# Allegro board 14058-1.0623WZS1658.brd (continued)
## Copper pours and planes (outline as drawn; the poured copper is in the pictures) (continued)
SB3V on L4: 140.15,234.43 140.4,234.68 144.09,234.68 144.21,234.56 144.21,231.25 142.69,229.73 108.78,229.73 107.89,230.62 107.89,231.63 110.69,234.43
SB5V on BOTTOM: 107.89,55.61 107.51,55.99 107.51,56.12 108.15,56.76 108.15,59.68 109.16,59.68 109.42,59.42 109.42,56.88 108.15,55.61
SB5V on BOTTOM: 63.19,51.68 62.93,51.93 62.93,55.28 62.97,55.32 62.97,55.9 63.32,56.25 69.28,56.25 71.06,54.47 72.46,54.47 72.84,54.09 72.84,51.93 71.19,51.93 70.88,52.23 69.74,52.23 69.28,52.69 68.52,52.69 68.14,52.31 65.22,52.31 64.59,51.68 ; 4 cut-outs
SB5V on BOTTOM: 93.16,63.11 92.91,63.36 92.91,65.65 91.76,66.79 91.76,70.6 94.81,73.65 96.97,73.65 97.22,73.39 97.22,72.5 96.97,72.25 95.45,72.25 93.03,69.84 93.03,67.68 94.05,66.66 94.05,63.36 93.8,63.11
SB5V on BOTTOM: 45.92,254.49 45.66,254.75 45.66,256.91 46.81,258.05 54.43,258.05 54.68,257.8 54.68,257.03 54.3,256.65 48.58,256.65 47.31,255.38 47.31,254.88 46.93,254.49
SB5V on L3: 62.81,52.69 62.81,51.8 63.06,51.55 79.57,51.55 85.67,57.64 89.99,57.64 91.13,58.79 91.13,60.06 93.03,61.96 93.03,62.72 93.54,63.23 93.8,63.23 94.05,63.49 94.05,63.99 93.8,64.25 92.78,64.25 91.38,62.85 90.37,62.85 87.45,59.93 86.05,59.93 79.06,52.95 63.06,52.95
SD_VDD2 on BOTTOM: 197.68,151.75 197.55,151.88 197.55,152.77 198.19,153.4 199.21,153.4 199.59,153.78 199.59,154.55 199.84,154.8 199.84,155.31 200.22,155.69 201.11,155.69 201.75,156.32 202.13,156.32 202.38,156.07 202.38,155.69 200.98,154.29 200.98,152.89 199.84,151.75 ; 3 cut-outs
SLEEVE_CON on TOP: 187.9,74.28 187.65,74.54 187.65,75.17 187.78,75.3 194.51,75.3 194.63,75.17 194.63,74.54 194.38,74.28 ; 4 cut-outs
SPKR_OUT_L+ on TOP: 162.38,28.56 161.99,28.94 161.99,30.47 162.88,31.36 166.57,31.36 166.69,31.23 166.69,30.21 166.19,29.7 164.79,29.7 163.65,28.56 ; 5 cut-outs
USBVCC01 on TOP: 186.25,117.21 185.74,117.72 184.98,117.72 184.73,117.97 184.73,119.24 185.11,119.62 188.79,119.62 188.92,119.75 189.81,119.75 190.32,120.26 193.11,120.26 193.36,120 193.36,119.37 192.73,118.73 191.46,118.73 189.93,117.21 ; 2 cut-outs
USBVCC01 on TOP: 176.85,90.16 176.47,90.54 176.47,99.3 177.62,100.44 182.57,100.44 184.09,101.97 191.2,101.97 193.74,99.43 193.74,97.78 192.98,97.01 184.47,97.01 182.06,94.6 182.06,94.22 180.28,92.44 179.27,92.44 178.76,91.93 178.76,90.54 178.38,90.16 ; 2 cut-outs
USBVCC01 on BOTTOM: 179.14,95.36 178.63,95.87 178.63,99.43 179.01,99.81 180.79,99.81 182.31,101.33 187.14,101.33 187.52,101.71 187.52,105.14 186.76,105.9 185.87,105.9 185.49,106.29 185.49,120.26 186.76,121.53 191.97,121.53 193.24,120.26 193.24,118.35 192.98,118.1 191.97,118.1 191.59,117.72 191.59,112.25 192.35,111.49 193.24,111.49 193.74,110.98 193.74,97.78 193.24,97.27 182.95,97.27 181.04,95.36
USBVCC89 on TOP: 116.02,15.35 115.96,15.42 115.39,15.42 113.99,16.81 113.99,23.35 112.21,25.13 112.21,26.15 112.85,26.78 116.02,26.78 116.15,26.91 116.27,26.91 116.78,27.42 121.61,27.42 122.12,26.91 122.12,23.61 121.99,23.48 121.99,19.04 123.51,17.51 123.51,15.61 123.26,15.35 ; 8 cut-outs
USBVCC89 on BOTTOM: 115.51,14.46 115.13,14.85 115.13,17.51 115.39,17.77 116.53,17.77 117.04,17.26 118.94,17.26 119.96,18.27 135.2,18.27 135.96,17.51 135.96,16.12 135.32,15.48 120.85,15.48 119.83,14.46
USBVCC1011 on TOP: 109.54,27.04 108.27,28.31 108.27,34.66 109.16,35.55 109.8,35.55 110.43,36.18 110.43,38.85 110.56,38.98 111.7,38.98 111.96,38.72 111.96,38.21 112.08,38.09 116.27,38.09 123.51,45.33 134.94,45.33 136.34,43.93 136.34,42.66 136.98,42.02 136.98,38.59 136.85,38.47 133.29,38.47 133.04,38.72 131.39,38.72 128.47,41.64 125.04,41.64 124.4,41.01 124.4,40.63 121.74,37.96 120.47,37.96 116.78,34.28 116.78,27.93 115.89,27.04 ; 8 cut-outs
USBVCCTP on TOP: 14.29,130.8 14.17,130.92 14.17,132.32 14.29,132.45 15.94,132.45 16.07,132.32 16.07,131.94 14.93,130.8
USBVCCTP on BOTTOM: 14.17,130.8 13.79,131.18 13.79,137.02 14.04,137.27 14.8,137.27 15.06,137.02 15.06,131.05 14.8,130.8
V_1P5_HDMI on TOP: 163.06,47.38 163.06,48.2 163.31,48.45 164,48.45 164.2,48.25 164.2,47.64 163.95,47.38
V_1P5_HDMI on TOP: 157.3,42.79 157.17,42.91 157.17,43.67 157.55,44.06 157.68,44.06 157.8,43.93 158.69,43.93 158.69,43.29 158.18,42.79
V_1P5_HDMI on TOP: 163.62,42.81 163.01,43.42 163.01,43.93 163.77,43.93 164.2,43.5 165.09,43.5 165.17,43.42 165.17,42.96 165.02,42.81
V_1P5_HDMI on TOP: 147.77,45.83 146.12,47.48 144.72,47.48 144.34,47.87 142.94,47.87 142.18,47.1 141.29,47.1 141.17,47.23 141.17,47.99 142.18,49.01 144.21,49.01 144.72,49.52 149.42,49.52 149.68,49.26 149.68,46.34 149.17,45.83 ; 3 cut-outs
V_1P5_HDMI on BOTTOM: 164.03,41.52 162.25,43.29 158.82,43.29 158.18,42.66 155.64,42.66 153.23,45.07 147.52,45.07 147.14,45.45 147.14,47.23 147.52,47.61 155.77,47.61 155.9,47.48 155.9,46.85 155.77,46.72 155.14,46.72 154.88,46.47 154.88,45.07 156.41,43.55 157.68,43.55 158.31,44.18 162.88,44.18 164.66,42.4 165.8,42.4 165.93,42.28 165.93,41.64 165.8,41.52 ; 1 cut-out
V_1P05_LAN on TOP: 63.57,24.09 63.47,24.19 63.47,24.52 62.98,25.01 62.98,25.89 63.16,25.89 64.18,24.88 64.18,24.17 64.1,24.09
V_1P05_LAN on BOTTOM: 60.01,23.86 59.51,24.37 57.73,24.37 56.71,25.39 56.71,31.61 56.97,31.86 61.16,31.86 61.79,31.23 61.79,30.47 61.54,30.21 60.01,30.21 59.76,29.96 59.12,29.96 58.74,30.34 58.11,30.34 57.98,30.21 57.98,28.05 58.36,27.67 59.12,27.67 59.25,27.55 59.25,26.15 59.63,25.77 64.59,25.77 64.71,25.64 64.71,24.24 64.33,23.86 ; 8 cut-outs
V_3_CARD on BOTTOM: 179.27,140.24 178.76,140.75 178.76,141.13 179.01,141.39 180.54,141.39 180.74,141.59 181.63,141.59 181.91,141.87 181.91,142.2 182.06,142.35 182.36,142.35 182.7,142.02 182.82,142.02 183.2,141.64 183.2,140.5 182.95,140.24 ; 4 cut-outs
V_3P3_A on TOP: 75.51,68.06 75.25,68.31 73.09,68.31 68.78,72.63 65.09,72.63 63.06,74.66 61.28,74.66 61.16,74.79 61.16,79.62 61.66,80.12 63.82,80.12 64.78,79.17 64.78,77.9 67,75.68 71.82,75.68 72.84,74.66 74.24,74.66 78.43,70.47 79.19,70.47 80.08,69.58 80.08,68.57 79.57,68.06 ; 2 cut-outs
V_3P3_A on BOTTOM: 102.58,63.59 102.48,63.69 102.48,64.27 102.56,64.35 103.14,64.35 103.4,64.6 103.4,64.91 104.01,65.52 105.99,65.52 106.5,65.01 106.5,64.25 106.24,63.99 105.86,63.99 105.61,64.25 105.61,64.63 105.48,64.76 104.84,64.76 104.54,64.45 104.54,64.2 103.93,63.59
V_3P3_A on BOTTOM: 79.11,67.12 78.3,67.93 77.79,67.93 77.41,68.31 77.41,69.33 77.79,69.71 79.7,69.71 80.08,69.33 80.08,68.13 79.95,68.01 79.95,67.12
V_3P3_A on BOTTOM: 75.38,44.69 74.36,45.71 74.36,50.43 75.35,50.43 75.53,50.25 75.53,49.29 76.4,48.42 76.4,46.09 76.65,45.83 78.3,45.83 78.56,45.58 78.56,44.94 78.3,44.69 ; 4 cut-outs
V_3P3_PCIVAUX on TOP: 135.07,226.55 134.94,226.68 134.94,226.69 134.69,226.95 131.79,226.95 131.66,227.07 131.66,229.61 131.79,229.74 135.85,229.74 136.23,229.36 136.23,228.33 139.9,228.33 140.79,227.44 140.79,227.06 140.28,226.55 ; 8 cut-outs
V_3P3_PCIVAUX on BOTTOM: 135.07,226.05 134.56,226.55 134.56,228.84 135.83,230.11 138.12,230.11 138.25,229.98 138.25,229.7 138.37,229.7 139.99,228.08 145.74,228.08 146.25,228.59 146.25,229.98 146.37,230.11 149.17,230.11 149.42,229.86 149.42,226.55 148.91,226.05
V_5_LCD1 on BOTTOM: 17.6,52.82 17.34,53.07 17.34,53.58 16.96,53.96 16.45,53.96 16.33,54.09 16.33,55.23 16.45,55.36 18.1,55.36 18.36,55.1 19.37,55.1 19.63,54.85 19.63,53.96 19.37,53.71 18.48,53.71 18.23,53.45 18.23,53.07 17.98,52.82 ; 1 cut-out
V_5_LCD2 on BOTTOM: 18.48,55.49 18.1,55.87 16.45,55.87 16.33,55.99 16.33,57.26 17.09,58.03 17.09,58.91 17.47,59.3 18.36,59.3 20.01,57.64 20.01,55.74 19.75,55.49 ; 3 cut-outs
V_5HDD on TOP: 23.82,113.78 22.17,115.43 20.9,115.43 20.39,115.94 20.39,126.22 20.9,126.73 22.68,126.73 23.95,125.46 28.39,125.46 28.77,125.08 28.77,114.16 28.39,113.78 ; 4 cut-outs
V_5P0_A on TOP: 75.13,54.47 74.87,54.72 74.87,60.18 75,60.31 78.94,60.31 79.19,60.06 79.19,55.1 78.56,54.47
V_5P0_A on BOTTOM: 77.59,50.91 77.46,51.04 77.46,51.47 78.05,52.06 78.05,52.82 77.92,52.95 77.03,52.95 76.02,51.93 74.36,51.93 74.36,53.83 75.13,54.6 75.13,62.98 75.99,63.84 75.99,64.73 76.52,65.26 78.05,65.26 78.43,65.65 79.95,65.65 79.95,64.76 80.33,64.38 80.33,51.93 79.95,51.55 78.81,51.55 78.76,51.6 78.63,51.6 77.95,50.91 ; 3 cut-outs
V_19_INV on TOP: 7.69,5.45 7.56,5.57 7.56,11.92 8.57,12.93 12.87,12.93 13.15,12.65 13.15,5.57 13.02,5.45
V_CPU_CORE on TOP: outline of 111 points within 34.99,179.24 83.51,229.09 ; 6 cut-outs
V_CPU_CORE on BOTTOM: 70.17,180.58 69.16,181.6 69.16,182.23 69.41,182.49 79.83,182.49 80.84,183.5 80.91,183.5 80.91,185.69 80.53,186.08 77.03,186.08 76.56,186.55 69.79,186.55 68.56,185.31 63.51,185.31 62.12,183.92 58.14,183.92 57.85,183.63 46.68,183.63 45.79,184.52 40.33,184.52 34.99,189.85 34.99,228.71 35.38,229.09 42.61,229.09 48.58,223.13 48.58,220.71 51.76,217.54 51.76,210.68 58.87,203.57 60.9,203.57 61.28,203.19 61.28,201.15 61.65,200.79 62.57,200.79 62.68,200.68 62.71,200.68 62.88,200.51 62.88,197.51 67.17,193.21 69.1,193.21 69.1,193.19 69.48,192.81 69.48,191.38 69.86,190.99 76.27,190.99 76.78,190.49 76.78,189.22 77.16,188.84 81.35,188.84 81.54,189.03 83.25,187.31 83.25,180.83 83,180.58 ; 8 cut-outs
V_CPU_CORE on L3: 68.15,196.26 64.97,199.43 63.95,199.43 61.34,202.05 61.34,203.19 61.01,203.52 58.91,203.52 51.76,210.68 51.76,220.2 50.62,221.35 50.62,223.76 46.3,228.08 39.95,228.08 38.93,229.09 35.38,229.09 34.99,228.71 34.99,189.85 40.33,184.52 49.09,184.52 51.11,182.5 52.41,182.5 55.7,179.22 81.42,179.22 83.2,181 83.2,189.32 82.49,190.04 73.48,190.04 68.15,195.37
V_CPU_CORE on L4: 38.3,186.04 44.52,186.04 45.92,187.44 48.58,187.44 50.92,189.77 54.88,189.77 55.31,189.34 57.02,189.34 57.3,189.62 62.05,189.62 63.34,188.33 63.34,188.05 64.33,187.06 64.33,181.34 64.2,181.22 64.2,180.33 64.97,179.56 68.78,179.56 69.54,180.33 73.73,180.33 77.67,184.26 77.67,189.85 77.41,190.11 73.86,190.11 68.78,195.19 68.78,197.85 60.01,206.62 60.01,214.74 44.27,230.49 36.01,230.49 34.87,229.35 34.87,189.47
V_CPU_GT on TOP: 69.99,195.09 69.1,195.98 69.1,198.27 64.77,202.61 63.19,202.61 62.94,202.86 62.94,207.66 62.5,208.1 62.5,208.17 62.24,208.43 61.61,208.43 60.38,209.65 60.38,214.75 53.79,221.35 53.79,233.03 60.9,240.14 76.14,240.14 77.16,241.16 77.16,243.32 80.84,247 80.84,250.3 81.48,250.94 90.24,250.94 90.87,250.3 90.87,246.24 91.38,245.73 100.91,245.73 102.43,244.21 106.75,244.21 107.26,243.7 107.26,238.87 103.96,235.57 99.51,235.57 96.84,232.9 96.84,222.49 84.91,210.55 77.03,210.55 76.14,209.66 76.14,204.71 76.55,204.3 76.55,201.57 77.67,200.45 77.67,199.28 78.05,198.9 79.9,198.9 80.28,198.52 80.28,195.22 80.15,195.09 ; 2 cut-outs
V_CPU_GT on BOTTOM: 69.23,195.22 69.1,195.35 69.1,196.87 69.11,196.88 69.03,196.96 69.03,198.27 63.95,203.35 63.9,203.35 62.5,204.74 62.5,205.63 60.38,207.75 60.39,207.76 60.39,214.74 53.79,221.35 53.79,233.03 61.16,240.4 82.62,240.4 87.57,245.35 96.34,245.35 96.72,245.73 100.91,245.73 102.43,244.21 106.75,244.21 107.26,243.7 107.26,238.87 103.96,235.57 99.51,235.57 96.84,232.9 96.84,229.73 88.97,221.86 82.28,221.86 74.94,214.52 74.94,204.11 76.52,202.53 76.52,200.47 78.05,198.94 79.88,198.94 80.28,198.54 80.28,195.24 80.27,195.22
V_CPU_GT on L3: 74.87,213.98 74.87,203.06 75,202.93 75.14,202.93 77.72,200.35 78.76,200.35 80.21,198.9 80.21,197.22 77.42,194.43 77.42,190.8 77.04,190.42 75.89,190.42 75.89,190.52 75.56,190.85 73.43,190.85 69.16,195.12 69.16,198.42 64.21,203.37 63.36,203.37 62.43,204.31 62.43,206.62 60.39,208.65 60.39,214.74 53.79,221.35 53.79,233.03 61.16,240.4 76.4,240.4 77.16,241.16 77.16,243.32 80.84,247 80.84,250.3 81.48,250.94 90.24,250.94 90.87,250.3 90.87,246.24 91.38,245.73 100.91,245.73 102.43,244.21 106.75,244.21 107.26,243.7 107.26,238.87 103.96,235.57 99.51,235.57 96.84,232.9 96.84,230.91 91.09,225.16 86.05,225.16
V_CPU_GT on L4: 76.27,215.89 76.27,213 76.22,212.95 76.27,212.9 76.27,201.26 77.51,200.02 80.17,200.02 80.53,199.66 80.53,194.97 77.42,191.85 77.42,190.8 77.04,190.42 73.86,190.42 69.16,195.12 69.16,198.42 63.26,204.32 63.26,204.36 60.39,207.23 60.39,214.74 53.79,221.35 53.79,233.03 61.16,240.4 76.4,240.4 77.16,241.16 77.16,243.32 80.84,247 80.84,250.3 81.48,250.94 90.24,250.94 90.87,250.3 90.87,246.24 91.38,245.73 100.91,245.73 102.43,244.21 106.75,244.21 107.26,243.7 107.26,238.87 103.96,235.57 99.51,235.57 96.84,232.9 96.84,230.91 92.11,226.17 86.56,226.17
V_CPU_GTX on BOTTOM: 66.11,198.11 65.86,198.36 65.86,198.74 65.47,199.12 64.97,199.12 64.08,200.01 63.32,200.01 63.06,200.27 63.06,200.77 62.81,201.03 62.3,201.03 62.17,201.15 62.17,201.66 61.92,201.92 61.54,201.92 61.41,202.04 61.41,202.42 61.66,202.68 64.33,202.68 66.24,200.77 67.25,200.77 67.76,200.27 67.76,198.49 67.38,198.11
V_CPU_IO on TOP: 66.75,174.67 66.62,174.8 66.62,175.3 66.75,175.43 67,175.43 68.02,176.45 69.85,176.45 71.7,178.29 71.7,179.82 71.82,179.95 71.82,179.98 73.8,179.98 73.93,179.85 73.93,178.83 73.86,178.76 73.86,175.25 73.3,174.69 71.29,174.69 71.09,174.89 70.76,174.89 70.56,174.69 70.38,174.69 69.8,175.27 69.3,175.27 68.73,174.69 68.48,174.69 68.01,175.16 67.37,175.16 66.88,174.67 ; 3 cut-outs
V_CPU_IO on TOP: 82.29,178.73 80.28,180.74 79.64,180.74 79.52,180.87 79.52,182.77 79.64,182.9 80.91,182.9 81.29,182.52 81.29,181.97 81.61,181.65 81.61,180.76 83,179.37 83.39,179.37 84.15,180.13 84.27,180.13 84.53,179.88 84.53,178.99 84.27,178.73
V_CPU_IO on TOP: 79.26,189.25 79.01,189.5 79.01,192.17 79.26,192.43 80.91,192.43 81.29,192.04 81.29,189.63 80.91,189.25
V_CPU_IO on TOP, BOTTOM: 45.79,175.25 45.41,175.63 45.41,180.96 45.66,181.22 48.58,181.22 48.96,180.83 48.96,175.63 48.58,175.25
V_CPU_IO on BOTTOM: 79.57,189.22 79.19,189.6 79.19,192.39 79.44,192.65 80.97,192.65 81.35,192.26 81.35,189.47 81.1,189.22
V_CPU_IO on L3: 55.7,178.8 72.71,178.8 73.73,177.79 73.73,175.75 73.48,175.5 64.46,175.5 61.03,172.07 56.46,172.07 53.79,174.74 47.06,174.74 46.81,174.99 46.81,180.96 47.31,181.47 53.03,181.47
V_CPU_IO on L4: 83.45,189.72 84.09,190.36 84.09,192.38 83,193.46 79.79,193.46 77.99,191.66 77.99,184.04 73.42,179.47 72.15,179.47 71.52,178.84 71.52,175.03 72.4,174.14 76.47,174.14 76.72,174.39 76.72,176.04 77.48,176.8 77.48,177.57 77.87,177.95 82.69,177.95 83.96,179.22 83.96,183.28 83.45,183.79
V_CPU_OPC on TOP: 82.75,194.3 82.37,194.68 82.37,197.22 82.49,197.34 83.25,197.34 83.38,197.22 83.38,196.96 83.25,196.84 83.25,196.71 83.51,196.46 83.51,196.2 83.38,196.07 83.38,195.69 84.02,195.06 84.4,195.06 84.52,195.19 84.78,195.19 84.91,195.06 84.91,194.8 84.4,194.3
V_CPU_OPC on BOTTOM: 80.84,196.07 80.71,196.2 80.71,196.96 81.1,197.34 82.75,197.34 83.13,196.96 83.13,196.33 82.87,196.07
V_CPU_SA on TOP: 37.41,160.51 35.5,162.42 35.5,173.21 35.76,173.47 43.5,173.47 44.01,172.96 44.01,162.17 43.63,161.78 40.71,161.78 39.44,160.51
V_CPU_SA on TOP: 73.73,172.89 73.48,173.14 73.48,173.22 73.45,173.22 72.9,173.78 72.59,173.78 72.39,173.58 71.37,173.58 71.09,173.86 70.69,173.86 70.56,173.73 70.33,173.73 70.2,173.86 69.8,173.86 69.7,173.75 69.39,173.75 69.29,173.86 68.93,173.86 68.83,173.75 68.5,173.75 68.43,173.83 68.04,173.83 67.94,173.73 67.64,173.73 67.51,173.86 67.51,174.24 67.99,174.72 68.3,174.72 68.45,174.57 68.88,174.57 69.01,174.69 69.26,174.69 69.37,174.59 69.72,174.59 69.74,174.57 73.35,174.57 73.48,174.69 73.48,174.7 74.11,175.34 74.11,177.79 75.76,177.79 76.4,178.42 76.4,179.22 76.78,179.6 77.1,179.6 77.27,179.44 78.43,179.44 78.68,179.18 78.68,176.26 77.54,175.12 77.54,173.27 77.16,172.89 ; 4 cut-outs
V_CPU_SA on BOTTOM: 76.02,174.23 75.51,174.74 74.49,174.74 74.24,174.99 74.24,178.42 74.75,178.93 78.68,178.93 79.19,178.42 79.19,176.26 77.16,174.23
V_CPU_SA on L3: 75.25,166.22 67.16,158.14 52.74,158.14 49.73,161.15 37.15,161.15 35.5,162.8 35.5,173.21 35.76,173.47 54.3,173.47 56.42,171.34 61.01,171.34 61.9,172.23 61.9,172.36 64.81,175.27 64.84,175.25 73.98,175.25 74.11,175.37 74.11,177.91 74.29,178.1 78.88,178.1 79.32,177.66 79.32,176.36 76.81,173.85 76.81,172.96 75.25,171.4
V_CPU_SA on L4: 72.28,172.23 72.28,173.63 72.53,173.88 76.47,173.88 76.85,174.26 76.85,175.92 77.61,176.68 77.61,177.44 77.87,177.69 78.63,177.69 78.88,177.44 78.88,176.55 77.87,175.53 77.87,174.39 77.48,174.01 77.48,174 77.01,173.52 77.01,172.26 75.71,170.96 74.06,170.96 72.91,172.11 72.4,172.11
V_SM on TOP: 108.27,124.45 108.02,124.7 108.02,125.59 107,126.61 105.73,126.61 104.34,128 104.34,131.3 104.59,131.56 107.13,131.56 107.26,131.43 107.26,128.64 107.51,128.38 111.96,128.38 114.24,130.67 114.24,136.38 114.88,137.02 121.63,137.02 125.04,133.62 125.04,130.42 121.23,126.61 114.24,126.61 112.08,124.45
V_SM on BOTTOM: 121.61,131.81 116.78,136.64 116.78,153.28 115,155.05 96.34,155.05 88.59,162.8 88.59,180.45 89.48,181.34 89.48,183.2 89.3,183.37 89.1,183.37 88.59,183.88 88.59,191.76 101.42,204.58 125.16,204.58 125.29,204.46 165.3,204.46 166.82,202.93 170.76,202.93 173.42,200.27 173.42,157.47 171.01,155.05 129.23,155.05 125.1,150.93 125.1,133.53 123.39,131.81 ; 59 cut-outs
V_SM_VTT on TOP: 157.8,130.42 155.14,133.08 151.71,133.08 151.07,133.72 151.07,134.86 151.83,135.62 156.28,135.62 158.69,133.21 162.12,133.21 164.53,135.62 169.87,135.62 170,135.5 170,134.23 166.19,130.42
V_SM_VTT on BOTTOM: 145.1,129.53 142.06,132.57 142.06,137.02 142.31,137.27 143.71,137.27 143.96,137.53 144.85,137.53 145.1,137.27 145.1,133.72 145.99,132.83 149.8,132.83 151.83,134.86 165.04,134.86 165.42,135.24 165.42,135.75 165.55,135.88 166.31,135.88 166.44,135.75 168.85,135.75 169.36,135.24 169.36,132.45 168.09,131.18 153.36,131.18 151.71,129.53 ; 7 cut-outs
VOUT_INV on TOP: 25.47,2.91 25.22,3.16 25.22,6.21 25.34,6.34 26.87,6.34 26.99,6.21 26.99,3.16 26.74,2.91
VOUT_INV on TOP: 25.34,6.84 25.22,6.97 25.22,9.13 25.34,9.26 26.87,9.26 26.99,9.13 26.99,6.97 26.87,6.84
VOUT_INV on BOTTOM: 25.09,6.64 25.09,8.88 24.71,9.26 19.75,9.26 18.42,10.59 15.75,10.59 15.44,10.91 15.44,11.67 15.56,11.8 15.82,11.8 16.07,11.54 19.12,11.54 19.5,11.16 20.26,11.16 20.9,11.8 26.36,11.8 28.26,9.89 35.38,9.89 36.26,9 36.26,6.59 36.01,6.34 27.25,6.34 27.23,6.32 25.41,6.32
VOUT_INV on L3: 25.47,9.38 26.74,9.38 27.12,9 27.12,3.16 26.99,3.03 25.22,3.03 25.09,3.16 25.09,9

Small or netless copper shapes (teardrops, artwork), in the pictures only: 7 on TOP, 8 on BOTTOM

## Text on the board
Ref Des/Silkscreen Bottom: F12.2A/6V | F17:2A/6V | F7:1.5A/6V
Ref Des/Silkscreen Top: PSWD | RTCRST | SERVICE_MODE | 1-2.CLR_CMOS | 1-2:NORMAL(DEFAULT) | EMPTY(DEFAULT) | 1-2:ME DISABLE | EMPTY:CLEAR PASSWORD | EMPTY:NORMAL(DEFAULT) | FAN_CPU | TOUCH | CS1027 | LVDS | PWRCN1 | CONVERTER | F21:2A/6V | CPU1 | Dell PN:D47TW | DCIN1 | Rev:A00 | X3:25MHZ | RJ1 | F19:2A/6V | F18:2A/6V | USB2 | USB1 | NGFF | F5:2A/6V | USB4 | X1:24MHZ | X5:27MHZ | USB3 | BATTERY | SPEAKER | WEBCAM | X2:32.768KHZ | SSUSB12 | SSUSB1 | SATAP1 | SATA ODD | SATA HDD | X9502:14.31818MHZ | LOUT1 | DIMM1 | HDMI OUT | DIMM2 | For DDR3L Only | F14:2A/6V | F20:1.5A/6V | F6:1.5A/6V | UHS1 | M2 | Sunflower-AIO | 14058-1 | D47TW | MADE IN TAIWAN
User.14: ID-LABEL-16-R | 270.00 | 62.98 | 22.98 | 0.00 | 248.60 | 163.60 | 85.00 | 6.90 | 192.00 | 198.90 | 212.00 | 205.00 | F | A | B | C | D | E | G | H | I | J | 1 | 2 | 3 | 4 | 5 | 6 | 7 | 8 | 9 | 10 | 11 | 12 | 13 | 14 | T | 14558-1 | Version | PCB No. | Created | Jerry Jiang | 14058 | Thickness | Date | 2015-4-23 | 1.2mm | Model | Wistron Corporation | Sunflower
User.23: Board Accuracy Check,Jun 23 16:46:49 2015,Passed | Dummy-Static-No Shape On Layer Check,Jun 23 16:46:49 2015,Passed | Split Plane Check,Jun 23 16:46:48 2015,Passed
User.24: AGND | GND
User.26: AGND | GND
User.29: ByImpedance:100.0@_REF_L1=("3.5/10.0(L1)")|_REF_L6=("3.5/10.0(L6)")|Type="DP"|_REF_L4=("4.0/9.0(L4)")|_REF_L3=("4.0/9.0(L3)")|imp="100.0" | ByImpedance:110.0@_REF_L1=("nil(L1)")|_REF_L6=("nil(L6)")|Type="DP"|_REF_L4=("3.5/13.0(L4)")|_REF_L3=("3.5/13.0(L3)")|imp="110.0" | ByImpedance:27.4@_REF_L1=("12.0(L1)")|_REF_L6=("12.0(L6)")|Type="SE"|_REF_L4=("16.0(L4)")|_REF_L3=("16.0(L3)")|imp="27.4" | ByImpedance:33.0@_REF_L1=("9.0(L1)")|_REF_L6=("9.0(L6)")|Type="SE"|_REF_L4=("12.0(L4)")|_REF_L3=("12.0(L3)")|imp="33.0" | ByImpedance:34.0@_REF_L1=("8.5(L1)")|_REF_L6=("8.5(L6)")|Type="SE"|_REF_L4=("11.5(L4)")|_REF_L3=("11.5(L3)")|imp="34.0" | ByImpedance:35.0@_REF_L1=("8.0(L1)")|_REF_L6=("8.0(L6)")|Type="SE"|_REF_L4=("10.5(L4)")|_REF_L3=("10.5(L3)")|imp="35.0" | ByImpedance:37.5@_REF_L1=("7.0(L1)")|_REF_L6=("7.0(L6)")|Type="SE"|_REF_L4=("9.5(L4)")|_REF_L3=("9.5(L3)")|imp="37.5" | ByImpedance:39.0@_REF_L1=("6.5(L1)")|_REF_L6=("6.5(L6)")|Type="SE"|_REF_L4=("9.0(L4)")|_REF_L3=("9.0(L3)")|imp="39.0" | ByImpedance:40.0@_REF_L1=("6.5(L1)")|_REF_L6=("6.5(L6)")|Type="SE"|_REF_L4=("8.5(L4)")|_REF_L3=("8.5(L3)")|imp="40.0" | ByImpedance:42.0@_REF_L1=("5.5(L1)")|_REF_L6=("5.5(L6)")|Type="SE"|_REF_L4=("7.5(L4)")|_REF_L3=("7.5(L3)")|imp="42.0" | ByImpedance:45.0@_REF_L1=("5.0(L1)")|_REF_L6=("5.0(L6)")|Type="SE"|_REF_L4=("6.5(L4)")|_REF_L3=("6.5(L3)")|imp="45.0" | ByImpedance:48.0@_REF_L1=("4.5(L1)")|_REF_L6=("4.5(L6)")|Type="SE"|_REF_L4=("5.5(L4)")|_REF_L3=("5.5(L3)")|imp="48.0" | ByImpedance:50.0@_REF_L1=("4.0(L1)")|_REF_L6=("4.0(L6)")|Type="SE"|_REF_L4=("5.0(L4)")|_REF_L3=("5.0(L3)")|imp="50.0" | ByImpedance:52.0@_REF_L1=("3.5(L1)")|_REF_L6=("3.5(L6)")|Type="SE"|_REF_L4=("4.5(L4)")|_REF_L3=("4.5(L3)")|imp="52.0" | ByImpedance:55.0@_REF_L1=("nil(L1)")|_REF_L6=("nil(L6)")|Type="SE"|_REF_L4=("4.0(L4)")|_REF_L3=("4.0(L3)")|imp="55.0" | ByImpedance:65.0@_REF_L1=("8.0/6.0(L1)")|_REF_L6=("8.0/6.0(L6)")|Type="DP"|_REF_L4=("9.0/5.0(L4)")|_REF_L3=("9.0/5.0(L3)")|imp="65.0" | ByImpedance:68.0@_REF_L1=("6.5/4.0(L1)")|_REF_L6=("6.5/4.0(L6)")|Type="DP"|_REF_L4=("7.5/4.0(L4)")|_REF_L3=("7.5/4.0(L3)")|imp="68.0" | ByImpedance:70.0@_REF_L1=("7.0/6.0(L1)")|_REF_L6=("7.0/6.0(L6)")|Type="DP"|_REF_L4=("8.0/6.0(L4)")|_REF_L3=("8.0/6.0(L3)")|imp="70.0" | ByImpedance:72.0@_REF_L1=("7.0/8.0(L1)")|_REF_L6=("7.0/8.0(L6)")|Type="DP"|_REF_L4=("7.0/5.0(L4)")|_REF_L3=("7.0/5.0(L3)")|imp="72.0" | ByImpedance:75.0@_REF_L1=("6.0/6.0(L1)")|_REF_L6=("6.0/6.0(L6)")|Type="DP"|_REF_L4=("7.0/6.0(L4)")|_REF_L3=("7.0/6.0(L3)")|imp="75.0" | ByImpedance:80.0@_REF_L1=("5.0/5.0(L1)")|_REF_L6=("5.0/5.0(L6)")|Type="DP"|_REF_L4=("6.0/6.0(L4)")|_REF_L3=("6.0/6.0(L3)")|imp="80.0" | ByImpedance:85.0@_REF_L1=("5.0/8.0(L1)" "4.0/4.5(L1)")|_REF_L6=("5.0/8.0(L6)" "4.0/4.5(L6)")|Type="DP"|_REF_L4=("5.0/5.5(L4)")|_REF_L3=("5.0/5.5(L3)")|imp="85.0" | ByImpedance:90.0@_REF_L1=("4.0/6.0(L1)")|_REF_L6=("4.0/6.0(L6)")|Type="DP"|_REF_L4=("5.0/8.0(L4)" "4.0/5.0(L4)")|_REF_L3=("5.0/8.0(L3)" "4.0/5.0(L3)")|imp="90.0" | ByImpedance:93.0@_REF_L1=("4.0/8.0(L1)" "3.5/5.5(L1)")|_REF_L6=("4.0/8.0(L6)" "3.5/5.5(L6)")|Type="DP"|_REF_L4=("5.0/9.0(L4)" "4.0/5.5(L4)")|_REF_L3=("5.0/9.0(L3)" "4.0/5.5(L3)")|imp="93.0" | ByImpedance:95.0@_REF_L1=("4.0/10.0(L1)" "3.5/6.0(L1)")|_REF_L6=("4.0/10.0(L6)" "3.5/6.0(L6)")|Type="DP"|_REF_L4=("4.0/6.5(L4)")|_REF_L3=("4.0/6.5(L3)")|imp="95.0" | LayerIndex:nil | Source:6-1.2-7c.xls | artWorks:("_REF_L3" "_REF_L4" "_REF_L6" "_REF_L1") | gtImpOutlineUsed:BOARD GEOMETRY/PANEL_OUTLINE
User.31: This gerber is just for your reference to find the DP impedance traces in layer L1. | DP IMPEDANCE TABLE: L1 | * - Denotes that WIDTH | is NOT used in this layer | inside board outline. | IMP(Ohm) | 65.0 | 68.0 | 70.0 | 72.0 | 75.0 | 80.0 | 85.0 | 90.0 | 93.0 | 95.0 | 100.0 | 110.0 | WIDTH(mils) | *8.0/6.0 | 6.5/4.0 | *7.0/6.0 | *7.0/8.0 | *6.0/6.0 | 5.0/5.0 | 5.0/8.0 | 4.0/4.5 | 4.0/6.0 | 4.0/8.0 | *3.5/5.5 | 4.0/10.0 | *3.5/6.0 | 3.5/10.0 | *nil | TYPE | DP
User.33: This gerber is just for your reference to find the SE impedance traces in layer L1. | SE IMPEDANCE TABLE: L1 | * - Denotes that WIDTH | is NOT used in this layer | inside board outline. | IMP(Ohm) | 27.4 | 33.0 | 34.0 | 35.0 | 37.5 | 39.0 | 40.0 | 42.0 | 45.0 | 48.0 | 50.0 | 52.0 | 55.0 | WIDTH(mils) | 12.0 | 9.0 | 8.5 | 8.0 | 7.0 | 6.5 | 5.5 | 5.0 | *4.5 | 4.0 | *3.5 | *nil | TYPE | SE
User.35: This gerber is just for your reference to find the DP impedance traces in layer L3. | DP IMPEDANCE TABLE: L3 | * - Denotes that WIDTH | is NOT used in this layer | inside board outline. | IMP(Ohm) | 65.0 | 68.0 | 70.0 | 72.0 | 75.0 | 80.0 | 85.0 | 90.0 | 93.0 | 95.0 | 100.0 | 110.0 | WIDTH(mils) | *9.0/5.0 | 7.5/4.0 | *8.0/6.0 | *7.0/5.0 | *7.0/6.0 | 6.0/6.0 | 5.0/5.5 | *5.0/8.0 | 4.0/5.0 | *5.0/9.0 | 4.0/5.5 | *4.0/6.5 | 4.0/9.0 | *3.5/13.0 | TYPE | DP
User.37: This gerber is just for your reference to find the SE impedance traces in layer L3. | SE IMPEDANCE TABLE: L3 | * - Denotes that WIDTH | is NOT used in this layer | inside board outline. | IMP(Ohm) | 27.4 | 33.0 | 34.0 | 35.0 | 37.5 | 39.0 | 40.0 | 42.0 | 45.0 | 48.0 | 50.0 | 52.0 | 55.0 | WIDTH(mils) | *16.0 | 12.0 | 11.5 | *10.5 | *9.5 | 9.0 | *8.5 | 7.5 | 6.5 | *5.5 | 5.0 | *4.5 | 4.0 | TYPE | SE
User.39: This gerber is just for your reference to find the DP impedance traces in layer L4. | DP IMPEDANCE TABLE: L4 | * - Denotes that WIDTH | is NOT used in this layer | inside board outline. | IMP(Ohm) | 65.0 | 68.0 | 70.0 | 72.0 | 75.0 | 80.0 | 85.0 | 90.0 | 93.0 | 95.0 | 100.0 | 110.0 | WIDTH(mils) | *9.0/5.0 | 7.5/4.0 | *8.0/6.0 | *7.0/5.0 | *7.0/6.0 | 6.0/6.0 | 5.0/5.5 | *5.0/8.0 | *4.0/5.0 | *5.0/9.0 | *4.0/5.5 | *4.0/6.5 | 4.0/9.0 | *3.5/13.0 | TYPE | DP
User.41: This gerber is just for your reference to find the SE impedance traces in layer L4. | SE IMPEDANCE TABLE: L4 | * - Denotes that WIDTH | is NOT used in this layer | inside board outline. | IMP(Ohm) | 27.4 | 33.0 | 34.0 | 35.0 | 37.5 | 39.0 | 40.0 | 42.0 | 45.0 | 48.0 | 50.0 | 52.0 | 55.0 | WIDTH(mils) | *16.0 | 12.0 | 11.5 | *10.5 | *9.5 | 9.0 | *8.5 | 7.5 | 6.5 | *5.5 | 5.0 | *4.5 | 4.0 | TYPE | SE
User.43: This gerber is just for your reference to find the DP impedance traces in layer L6. | DP IMPEDANCE TABLE: L6 | * - Denotes that WIDTH | is NOT used in this layer | inside board outline. | IMP(Ohm) | 65.0 | 68.0 | 70.0 | 72.0 | 75.0 | 80.0 | 85.0 | 90.0 | 93.0 | 95.0 | 100.0 | 110.0 | WIDTH(mils) | *8.0/6.0 | *6.5/4.0 | *7.0/6.0 | *7.0/8.0 | *6.0/6.0 | 5.0/5.0 | 5.0/8.0 | 4.0/4.5 | *4.0/6.0 | 4.0/8.0 | *3.5/5.5 | *4.0/10.0 | *3.5/6.0 | 3.5/10.0 | *nil | TYPE | DP
User.45: This gerber is just for you reference to find the differential traces in layer BOTTOM | This gerber is just for you reference to find the differential traces in layer L3 | This gerber is just for you reference to find the differential traces in layer L4 | This gerber is just for you reference to find the differential traces in layer TOP | Note:Refer to DRILL layer for ELLIPSE drill direction | FIGURE | SIZE | 10.0 | 12.0 | 16.0 | 20.0 | 28.0 | 30.0 | 36.0 | 37.0 | 39.0 | 40.0 | 60.0 | 91.0 | 109.0 | 158.0 | 34.0 | 42.0 | 44.0 | 50.0 | 54.0 | 63.0 | 86.0 | 130.0 | 134.0 | 138.0 | 150.0 | 178.0 | 56.0x24.0 | 60.0x24.0 | 60.0x28.0 | 67.0x28.0 | 67.0x30.0 | 67.0x32.0 | 91.0x28.0 | 156.0x32.0 | 166.0x32.0 | 197.0x178.0 | DRILL CHART: TOP to BOTTOM | ALL UNITS ARE IN MILS | PLATED | NON-PLATED | QTY | 1710 | 3613 | 1399 | 48 | 18 | 14 | 16 | 46 | 15 | 4 | 8 | 1 | 6 | 2 | 3 | 5 | This gerber is just for your reference to find the SE impedance traces in layer L6. | SE IMPEDANCE TABLE: L6 | * - Denotes that WIDTH | is NOT used in this layer | inside board outline. | Sunflower-AIO | Model | 826646 | ECO | PCB_NO | 14058 | VER. | Layer | DRILL | L1 | L2GND | L3 | TMASK | TPLACE | TSILK | TSMD | Designer | Jerry J | IMP(Ohm) | 27.4 | 33.0 | 35.0 | 37.5 | 45.0 | 48.0 | 52.0 | 55.0 | Date | 06/23/2015 | WIDTH(mils) | *9.0 | 8.5 | 8.0 | 7.0 | 6.5 | 5.5 | 5.0 | *4.5 | 4.0 | *3.5 | *nil | TYPE | SE | BMASK | BPLACE | BSILK | BSMD | L4 | L5GND | L6
